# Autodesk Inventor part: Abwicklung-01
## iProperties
Shininess: 25.0
Length Units: 11269
Angle Units: 11279
Time Units: 11290
Mass Units: 11283
Length Display Precision: 3
Angle Display Precision: 2
Created: 2005-02
Part Number: Abwicklung-01
Material: S355NC
Document SubType Name: Blech
Designer: mczerniecki
Density: 0.0
Volumn: 0.0
Area: 0.0
PropertySet Name: Model Information
Control State: 0
Master: False
Checked Out: False
SPI-USE-INCH: False
SPI-THICKNESS: 4.0
SPI-MATERIAL: Neutral
SPI-MACHINE: Neutral
Author: mczerniecki
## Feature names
1. Extrusion1
2. Extrusion2
3. Eckenrundung1
4. Eckenfase1
5. Extrusion3
6. Extrusion4
7. Rechteckige Anordnung1 [Rectangular Pattern]
8. Extrusion7
9. Extrusion8
10. Rundung1 [Fillet]
11. Biegung24
12. Biegung25
13. Biegung26
14. Biegung27
15. Biegung28
16. Biegung29
17. Biegung30
18. Biegung31
19. Biegung32
20. Biegung33
21. Biegung34
22. Biegung35
23. Biegung36
24. Biegung37
25. Biegung38
26. Biegung39
27. Extrusion9
28. Extrusion10
29. Rundung2 [Fillet]
30. Rundung3 [Fillet]
31. Rundung4 [Fillet]
32. Rundung5 [Fillet]
33. ExtrusionAbwicklung1
